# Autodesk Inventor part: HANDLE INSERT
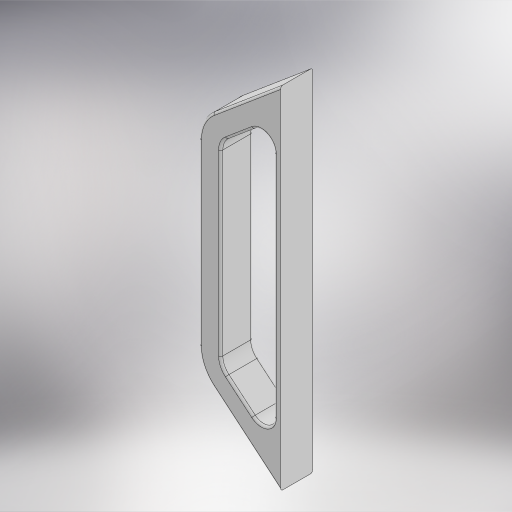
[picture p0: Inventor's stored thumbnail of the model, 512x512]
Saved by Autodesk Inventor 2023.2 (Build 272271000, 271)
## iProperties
Created: 2022-12
Part Number: HANDLE INSERT
Material: Generic
Document SubType Name: Modeling
Designer: AR
Mass: 34.009 g
Surface Area: 135.411 cm^2
Volume: 34.009 cm^3
Density: 1 g/cm^3
Appearance: Default
Author: AR
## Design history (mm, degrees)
derived "_2 SPOOL CORD WRAP MP.ipt"
feature "HANDLE INSERT::_2 SPOOL CORD WRAP MP.ipt" dims "d0" = 10
tag "TaggingFeature1"
node "HANDLE INSERT"
